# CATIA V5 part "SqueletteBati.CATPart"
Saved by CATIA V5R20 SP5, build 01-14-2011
Part number: SqueletteBati
Publications: "Droite.1", "Droite.2", "Plan.3"
Bounding box of the stored display mesh (mm): x 0 to 0, y 0 to 350, z -30 to 70
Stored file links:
  F:\IAO_bmadec\bmadecf\SqueletteBati.CATPart
  F:\IAO_bmadec\bmadecf\squelette.CATProduct
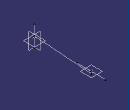
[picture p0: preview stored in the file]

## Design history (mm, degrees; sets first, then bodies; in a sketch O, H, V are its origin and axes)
Set1
  Plane1: linked copy from another document
  Point1: linked copy from another document
  Plane2: linked copy from another document
  Point2: linked copy from another document
Set2
  Line1: type Normal, RefPoint Point1, RefSkin Plane1, Start -50, End 50
  Line2: type Normal, RefPoint Point2, RefSkin Plane2, Start -70, End 70
  Plane3: type OffsetPt, RefPlane Plane1, RefPoint Point2
  Line3: type Normal, RefPoint Point2, RefSkin Plane3, Start 0, End 10
  Line4: type PtPt, FirstPoint Point1, SecondPoint vertex of Line3
Body1 (main body)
